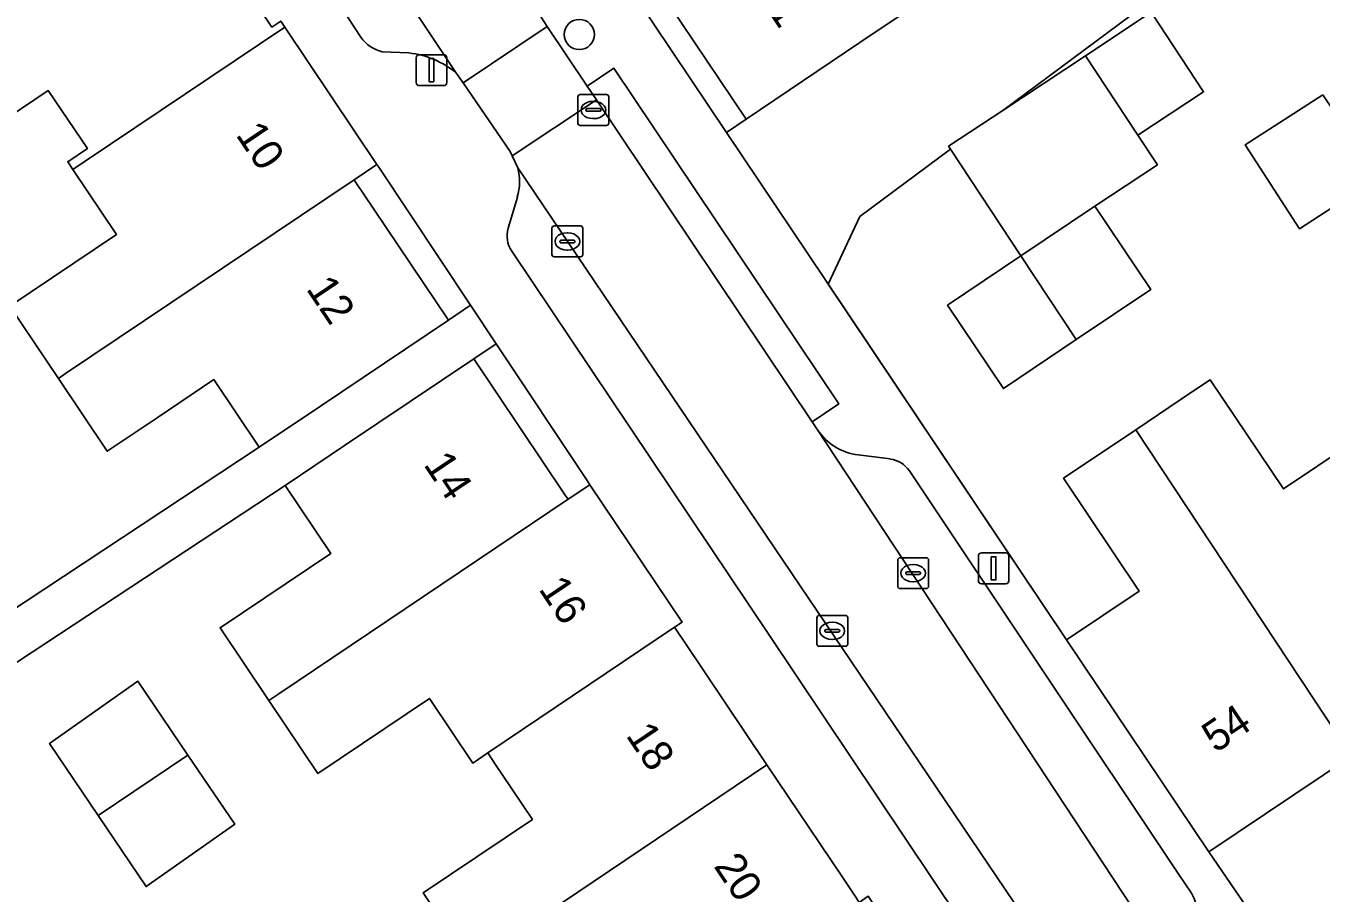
# Model space of a CAD drawing. Extents: x 158352 to 159489, y 383828 to 384603.
# Drawn here: x 158862.39 to 158904.38, y 384139.5 to 384167.59 of the extents above; entities that cross this region are included whole.
import ezdxf

# ---------------------------------------------------------------- set-up
doc = ezdxf.new("R2010")
doc.units = 0
for name, color, linetype in [('IMGEO_Boom', 7, 'Continuous'), ('IMGEO_Erf', 7, 'Continuous'), ('IMGEO_Kolk', 7, 'Continuous'), ('IMGEO_Lichtmast', 7, 'Continuous'), ('IMGEO_Muur', 7, 'Continuous'), ('IMGEO_Pand', 7, 'Continuous'), ('IMGEO_Pand_nummerreeks', 7, 'Continuous'), ('IMGEO_Parkeervlak_open', 7, 'Continuous'), ('IMGEO_Rijbaan_lokaal_open', 7, 'Continuous'), ('IMGEO_Voetpad_open', 7, 'Continuous')]:
    doc.layers.add(name, color=color, linetype=linetype)

msp = doc.modelspace()

# ---------------------------------------------------------------- linework, layer by layer
at = {"layer": 'IMGEO_Boom'}
msp.add_circle((158880.328, 384167.313), 0.489, dxfattribs=at)
at = {"layer": 'IMGEO_Erf'}
for points in [[(158942.263, 384168.715), (158937.66, 384165.622), (158933.069, 384162.537), (158933.874, 384161.338), (158929.263, 384158.239), (158928.917, 384158.007), (158928.717, 384158.105), (158924.553, 384155.307), (158919.952, 384152.215), (158915.351, 384149.124), (158910.891, 384146.127), (158911.02, 384145.936), (158910.878, 384145.84), (158906.196, 384142.695), (158905.358, 384143.942), (158900.735, 384140.836), (158902.964, 384137.583), (158985.981, 384193.365)], [(158907.21, 384174.62), (158894.054, 384164.852), (158896.733, 384166.624), (158898.863, 384168.033), (158900.566, 384165.459), (158898.436, 384164.05), (158899.07, 384163.091), (158897.04, 384161.748), (158898.851, 384159.05), (158896.439, 384157.43), (158894.077, 384155.844), (158892.266, 384158.542), (158894.646, 384160.141), (158892.361, 384163.595), (158889.423, 384161.414), (158888.397, 384159.227), (158896.123, 384147.701), (158898.481, 384149.285), (158896.028, 384152.938), (158898.369, 384154.511), (158900.179, 384155.727), (158900.779, 384156.13), (158903.155, 384152.593), (158905.348, 384154.067)], [(158855.372, 384144.324), (158869.956, 384153.946), (158868.486, 384156.135), (158866.609, 384154.875), (158865.934, 384154.422), (158865.029, 384153.814), (158863.444, 384156.173), (158861.868, 384158.518), (158865.324, 384160.84), (158863.911, 384162.943), (158863.746, 384163.189), (158864.381, 384163.616), (158863.115, 384165.499), (158859.582, 384163.125)], [(158906.237, 384162.682), (158903.677, 384161.02), (158901.912, 384163.736), (158904.435, 384165.362)], [(158876.811, 384137.203), (158875.264, 384139.505), (158878.807, 384141.886), (158877.828, 384143.343), (158877.602, 384143.679), (158877.359, 384144.04), (158876.876, 384143.715), (158875.47, 384145.809), (158871.853, 384143.379), (158870.267, 384145.739), (158868.685, 384148.094), (158872.269, 384150.502), (158870.79, 384152.704), (158856.183, 384143.092)]]:
    msp.add_lwpolyline(points, dxfattribs=at)
for points in [[(158882.786, 384168.968), (158882.152, 384168.541), (158885.101, 384164.143), (158885.743, 384164.573)], [(158873.827, 384163.017), (158873.766, 384163.107), (158873.028, 384162.611), (158873.089, 384162.521), (158873.668, 384161.659), (158876.084, 384158.063), (158876.803, 384158.541)], [(158877.632, 384157.295), (158876.905, 384156.812), (158879.171, 384153.438), (158879.875, 384152.391), (158879.964, 384152.258), (158880.668, 384152.731), (158880.579, 384152.864)], [(158867.639, 384143.972), (158869.158, 384141.73), (158866.287, 384139.711), (158864.727, 384142.014), (158863.15, 384144.342), (158866.021, 384146.361)]]:
    msp.add_lwpolyline(points, close=True, dxfattribs=at)
at = {"layer": 'IMGEO_Kolk'}
for p, q in [((158880.285, 384164.442), (158880.285, 384165.294)), ((158880.36, 384165.368), (158881.212, 384165.368)), ((158881.286, 384165.294), (158881.286, 384164.442)), ((158880.544, 384164.862), (158880.544, 384164.874)), ((158880.982, 384164.825), (158880.584, 384164.825)), ((158880.587, 384164.911), (158880.985, 384164.911)), ((158880.773, 384165.148), (158880.798, 384165.148)), ((158881.028, 384164.874), (158881.028, 384164.862)), ((158880.796, 384164.588), (158880.771, 384164.588)), ((158881.212, 384164.368), (158880.36, 384164.368)), ((158879.442, 384160.185), (158879.442, 384161.037)), ((158879.517, 384161.111), (158880.369, 384161.111)), ((158880.443, 384161.037), (158880.443, 384160.185)), ((158879.701, 384160.605), (158879.701, 384160.617)), ((158879.744, 384160.654), (158880.142, 384160.654)), ((158879.93, 384160.891), (158879.955, 384160.891)), ((158880.185, 384160.617), (158880.185, 384160.605)), ((158880.139, 384160.568), (158879.741, 384160.568)), ((158879.953, 384160.331), (158879.928, 384160.331)), ((158880.369, 384160.111), (158879.517, 384160.111)), ((158890.651, 384149.44), (158890.651, 384150.292)), ((158890.726, 384150.366), (158891.578, 384150.366)), ((158891.139, 384150.146), (158891.164, 384150.146)), ((158891.652, 384150.292), (158891.652, 384149.44)), ((158890.91, 384149.86), (158890.91, 384149.872)), ((158891.348, 384149.823), (158890.95, 384149.823)), ((158890.953, 384149.909), (158891.351, 384149.909)), ((158891.394, 384149.872), (158891.394, 384149.86)), ((158891.578, 384149.366), (158890.726, 384149.366)), ((158891.162, 384149.586), (158891.137, 384149.586)), ((158888.103, 384148.495), (158888.955, 384148.495)), ((158888.028, 384147.569), (158888.028, 384148.421)), ((158888.33, 384148.038), (158888.728, 384148.038)), ((158888.516, 384148.275), (158888.541, 384148.275)), ((158889.029, 384148.421), (158889.029, 384147.569)), ((158888.287, 384147.989), (158888.287, 384148.001)), ((158888.725, 384147.952), (158888.327, 384147.952)), ((158888.539, 384147.715), (158888.514, 384147.715)), ((158888.771, 384148.001), (158888.771, 384147.989)), ((158888.955, 384147.495), (158888.103, 384147.495))]:
    msp.add_line(p, q, dxfattribs=at)
for points in [[(158880.285, 384164.442), (158880.285, 384165.294)], [(158880.36, 384165.368), (158881.212, 384165.368)], [(158881.286, 384165.294), (158881.286, 384164.442)], [(158881.212, 384164.368), (158880.36, 384164.368)], [(158879.442, 384160.185), (158879.442, 384161.037)], [(158879.517, 384161.111), (158880.369, 384161.111)], [(158880.443, 384161.037), (158880.443, 384160.185)], [(158880.369, 384160.111), (158879.517, 384160.111)], [(158890.651, 384149.44), (158890.651, 384150.292)], [(158890.726, 384150.366), (158891.578, 384150.366)], [(158891.652, 384150.292), (158891.652, 384149.44)], [(158891.578, 384149.366), (158890.726, 384149.366)], [(158888.103, 384148.495), (158888.955, 384148.495)], [(158888.028, 384147.569), (158888.028, 384148.421)], [(158889.029, 384148.421), (158889.029, 384147.569)], [(158888.955, 384147.495), (158888.103, 384147.495)]]:
    msp.add_lwpolyline(points, dxfattribs=at)
for centre, radius, start, end in [((158880.362, 384165.292), 0.0765, 91.552, 178.448), ((158880.362, 384165.292), 0.0765, 91.552, 178.448), ((158881.21, 384165.292), 0.0765, 1.552, 88.448), ((158881.21, 384165.292), 0.0765, 1.552, 88.448), ((158880.584, 384164.871), 0.0403, 85.8775, 175.7526), ((158880.581, 384164.861), 0.0366, 178.938, 274.7102), ((158880.985, 384164.868), 0.043, 264.8664, 352.4533), ((158880.989, 384164.873), 0.0386, 1.7309, 96.639), ((158880.362, 384164.444), 0.0765, 181.552, 268.448), ((158880.362, 384164.444), 0.0765, 181.552, 268.448), ((158881.21, 384164.444), 0.0765, 271.552, 358.448), ((158881.21, 384164.444), 0.0765, 271.552, 358.448), ((158879.519, 384161.035), 0.0765, 91.552, 178.448), ((158879.519, 384161.035), 0.0765, 91.552, 178.448), ((158880.367, 384161.035), 0.0765, 1.552, 88.448), ((158880.367, 384161.035), 0.0765, 1.552, 88.448), ((158879.741, 384160.614), 0.0403, 85.8775, 175.7526), ((158880.146, 384160.616), 0.0386, 1.7309, 96.639), ((158879.738, 384160.604), 0.0366, 178.938, 274.7102), ((158880.142, 384160.611), 0.043, 264.8664, 352.4533), ((158879.519, 384160.187), 0.0765, 181.552, 268.448), ((158879.519, 384160.187), 0.0765, 181.552, 268.448), ((158880.367, 384160.187), 0.0765, 271.552, 358.448), ((158880.367, 384160.187), 0.0765, 271.552, 358.448), ((158890.728, 384150.29), 0.0765, 91.552, 178.448), ((158890.728, 384150.29), 0.0765, 91.552, 178.448), ((158891.576, 384150.29), 0.0765, 1.552, 88.448), ((158891.576, 384150.29), 0.0765, 1.552, 88.448), ((158890.95, 384149.869), 0.0403, 85.8775, 175.7526), ((158890.947, 384149.859), 0.0366, 178.938, 274.7102), ((158891.351, 384149.866), 0.043, 264.8664, 352.4533), ((158891.355, 384149.871), 0.0386, 1.7309, 96.639), ((158890.728, 384149.442), 0.0765, 181.552, 268.448), ((158890.728, 384149.442), 0.0765, 181.552, 268.448), ((158891.576, 384149.442), 0.0765, 271.552, 358.448), ((158891.576, 384149.442), 0.0765, 271.552, 358.448), ((158888.105, 384148.419), 0.0765, 91.552, 178.448), ((158888.105, 384148.419), 0.0765, 91.552, 178.448), ((158888.953, 384148.419), 0.0765, 1.552, 88.448), ((158888.953, 384148.419), 0.0765, 1.552, 88.448), ((158888.327, 384147.998), 0.0403, 85.8775, 175.7526), ((158888.732, 384148), 0.0386, 1.7309, 96.639), ((158888.324, 384147.988), 0.0366, 178.938, 274.7102), ((158888.728, 384147.995), 0.043, 264.8664, 352.4533), ((158888.105, 384147.571), 0.0765, 181.552, 268.448), ((158888.105, 384147.571), 0.0765, 181.552, 268.448), ((158888.953, 384147.571), 0.0765, 271.552, 358.448), ((158888.953, 384147.571), 0.0765, 271.552, 358.448)]:
    msp.add_arc(centre, radius, start, end, dxfattribs=at)
for centre, major_axis, ratio, start_param, end_param in [((158880.772, 384164.868), (-0.387, 0.002), 0.722429, 4.712389, 7.853982), ((158880.797, 384164.868), (-0.39, 0.002), 0.717154, 1.570796, 4.712389), ((158879.929, 384160.611), (-0.387, 0.002), 0.722429, 4.712389, 7.853982), ((158879.954, 384160.611), (-0.39, 0.002), 0.717154, 1.570796, 4.712389), ((158891.138, 384149.866), (-0.387, 0.002), 0.722429, 4.712389, 7.853982), ((158891.163, 384149.866), (-0.39, 0.002), 0.717154, 1.570796, 4.712389), ((158888.515, 384147.995), (-0.387, 0.002), 0.722429, 4.712389, 7.853982), ((158888.54, 384147.995), (-0.39, 0.002), 0.717154, 1.570796, 4.712389)]:
    msp.add_ellipse(centre, major_axis=major_axis, ratio=ratio, start_param=start_param, end_param=end_param, dxfattribs=at)
at = {"layer": 'IMGEO_Lichtmast'}
for p, q in [((158875.043, 384165.758), (158875.043, 384166.558)), ((158875.043, 384166.558), (158875.043, 384165.758)), ((158875.143, 384166.658), (158875.933, 384166.658)), ((158875.933, 384166.658), (158875.143, 384166.658)), ((158876.033, 384166.558), (158876.033, 384165.758)), ((158876.033, 384165.758), (158876.033, 384166.558)), ((158875.933, 384165.658), (158875.143, 384165.658)), ((158875.143, 384165.658), (158875.933, 384165.658)), ((158893.265, 384149.619), (158893.265, 384150.419)), ((158893.265, 384150.419), (158893.265, 384149.619)), ((158893.365, 384150.519), (158894.155, 384150.519)), ((158894.155, 384150.519), (158893.365, 384150.519)), ((158894.255, 384150.419), (158894.255, 384149.619)), ((158894.255, 384149.619), (158894.255, 384150.419)), ((158894.155, 384149.519), (158893.365, 384149.519)), ((158893.365, 384149.519), (158894.155, 384149.519))]:
    msp.add_line(p, q, dxfattribs=at)
for points in [[(158875.463, 384166.533), (158875.613, 384166.533), (158875.613, 384165.783), (158875.463, 384165.783), (158875.463, 384166.533)], [(158893.685, 384150.394), (158893.835, 384150.394), (158893.835, 384149.644), (158893.685, 384149.644), (158893.685, 384150.394)]]:
    msp.add_lwpolyline(points, dxfattribs=at)
for centre, start, end in [((158875.143, 384166.558), 90, 180), ((158875.143, 384166.558), 90, 180), ((158875.933, 384166.558), 0, 90), ((158875.933, 384166.558), 360, 90), ((158875.143, 384165.758), 180, 270), ((158875.143, 384165.758), 180, 270), ((158875.933, 384165.758), 270, 0), ((158875.933, 384165.758), 270, 0), ((158893.365, 384150.419), 90, 180), ((158893.365, 384150.419), 90, 180), ((158894.155, 384150.419), 0, 90), ((158894.155, 384150.419), 360, 90), ((158893.365, 384149.619), 180, 270), ((158893.365, 384149.619), 180, 270), ((158894.155, 384149.619), 270, 0), ((158894.155, 384149.619), 270, 0)]:
    msp.add_arc(centre, 0.1, start, end, dxfattribs=at)
at = {"layer": 'IMGEO_Muur'}
msp.add_lwpolyline([(158888.276, 384159.407), (158896.123, 384147.701)], dxfattribs=at)
at = {"layer": 'IMGEO_Pand'}
for points in [[(158882.044, 384168.696), (158882.152, 384168.541), (158882.786, 384168.968), (158885.743, 384164.573), (158889.892, 384167.365), (158891.843, 384168.678), (158890.409, 384170.81), (158893.929, 384173.179), (158892.302, 384175.597)], [(158858.024, 384165.444), (158859.582, 384163.125), (158863.115, 384165.499), (158864.381, 384163.616), (158863.746, 384163.189), (158863.911, 384162.943), (158864.307, 384163.209), (158870.778, 384167.555), (158870.648, 384167.748), (158870.361, 384167.555), (158867.501, 384171.811), (158858.355, 384165.667)], [(158896.733, 384166.624), (158898.411, 384164.087), (158898.436, 384164.05), (158900.566, 384165.459), (158898.863, 384168.033)], [(158873.028, 384162.611), (158873.766, 384163.107), (158870.778, 384167.555), (158864.307, 384163.209), (158863.911, 384162.943), (158865.324, 384160.84), (158861.868, 384158.518), (158863.444, 384156.173), (158863.678, 384156.331)], [(158898.436, 384164.05), (158898.411, 384164.087), (158896.733, 384166.624), (158894.054, 384164.852), (158892.298, 384163.691), (158892.361, 384163.595), (158894.646, 384160.141), (158897.04, 384161.748), (158899.07, 384163.091)], [(158904.435, 384165.362), (158901.912, 384163.736), (158903.677, 384161.02), (158906.237, 384162.682)], [(158873.028, 384162.611), (158863.678, 384156.331), (158863.444, 384156.173), (158865.029, 384153.814), (158865.934, 384154.422), (158866.609, 384154.875), (158868.486, 384156.135), (158869.956, 384153.946), (158871.934, 384155.275), (158876.084, 384158.063), (158873.668, 384161.659), (158873.089, 384162.521)], [(158894.646, 384160.141), (158896.439, 384157.43), (158898.851, 384159.05), (158897.04, 384161.748)], [(158894.646, 384160.141), (158892.266, 384158.542), (158894.077, 384155.844), (158896.439, 384157.43)], [(158879.964, 384152.258), (158879.875, 384152.391), (158879.171, 384153.438), (158876.905, 384156.812), (158872.755, 384154.024), (158870.79, 384152.704), (158872.269, 384150.502), (158868.685, 384148.094), (158870.267, 384145.739), (158870.586, 384145.953)], [(158906.084, 384152.973), (158905.348, 384154.067), (158903.155, 384152.593), (158900.779, 384156.13), (158900.179, 384155.727), (158898.369, 384154.511), (158905.358, 384143.942), (158906.196, 384142.695), (158910.878, 384145.84)], [(158905.358, 384143.942), (158898.369, 384154.511), (158896.028, 384152.938), (158898.481, 384149.285), (158896.123, 384147.701), (158900.735, 384140.836)], [(158883.417, 384148.111), (158883.662, 384148.276), (158880.668, 384152.731), (158879.964, 384152.258), (158870.586, 384145.953), (158870.267, 384145.739), (158871.853, 384143.379), (158875.47, 384145.809), (158876.876, 384143.715), (158877.359, 384144.04)], [(158886.41, 384143.657), (158883.729, 384147.646), (158883.501, 384147.986), (158883.417, 384148.111), (158877.359, 384144.04), (158877.602, 384143.679), (158877.828, 384143.343), (158878.807, 384141.886), (158875.264, 384139.505), (158876.811, 384137.203), (158877.197, 384137.463)], [(158864.727, 384142.014), (158867.639, 384143.972), (158866.021, 384146.361), (158863.15, 384144.342)], [(158864.727, 384142.014), (158866.287, 384139.711), (158869.158, 384141.73), (158867.639, 384143.972)], [(158889.404, 384139.201), (158889.293, 384139.366), (158888.836, 384140.046), (158886.41, 384143.657), (158877.197, 384137.463), (158876.811, 384137.203), (158878.423, 384134.804), (158881.967, 384137.186), (158883.348, 384135.13)]]:
    msp.add_lwpolyline(points, close=True, dxfattribs=at)
at = {"layer": 'IMGEO_Parkeervlak_open'}
for points in [[(158876.351, 384166.052), (158876.113, 384166.409), (158862.48, 384186.854)], [(158861.63, 384184.958), (158873.249, 384167.231)], [(158873.94, 384166.752), (158874.808, 384166.715)], [(158898.842, 384132.651), (158878.334, 384162.992)], [(158878.32, 384162.047), (158878.023, 384161.043)], [(158878.138, 384160.295), (158886.499, 384147.841), (158894.388, 384136.057), (158895.769, 384133.994)], [(158888.055, 384154.504), (158900.101, 384136.239)], [(158890.408, 384153.563), (158889.366, 384153.695)], [(158900.172, 384139.502), (158899.767, 384140.107), (158891.029, 384153.179)]]:
    msp.add_lwpolyline(points, dxfattribs=at)
for centre, radius, start, end in [((158874.24, 384167.923), 1.209, 214.9225, 255.6182), ((158874.506, 384163.886), 2.846, 49.5842, 83.9111), ((158876.642, 384162.544), 1.75, 343.4873, 14.8152), ((158878.876, 384160.791), 0.889, 163.5621, 213.9187), ((158889.598, 384155.538), 1.858, 213.8247, 262.819), ((158890.295, 384152.685), 0.885, 33.9048, 82.6335), ((158899.467, 384139.027), 0.85, 340.9972, 34.0024)]:
    msp.add_arc(centre, radius, start, end, dxfattribs=at)
at = {"layer": 'IMGEO_Rijbaan_lokaal_open'}
for points in [[(158865.197, 384188.669), (158862.48, 384186.854), (158876.113, 384166.409), (158876.351, 384166.052), (158876.56, 384165.749), (158879.291, 384167.574), (158879, 384168.028)], [(158880.587, 384165.641), (158879.291, 384167.574), (158876.56, 384165.749), (158878.091, 384163.528), (158878.157, 384163.383), (158880.883, 384165.199)]]:
    msp.add_lwpolyline(points, close=True, dxfattribs=at)
for points in [[(158888.055, 384154.504), (158887.877, 384154.77), (158880.883, 384165.199), (158878.157, 384163.383), (158878.334, 384162.992), (158898.842, 384132.651), (158901.467, 384128.786), (158904.315, 384134.226)], [(158900.779, 384135.251), (158900.452, 384135.707), (158900.101, 384136.239), (158888.055, 384154.504)]]:
    msp.add_lwpolyline(points, dxfattribs=at)
at = {"layer": 'IMGEO_Voetpad_open'}
for points in [[(158904.315, 384134.226), (158902.964, 384137.583), (158900.735, 384140.836), (158896.123, 384147.701), (158888.397, 384159.227), (158888.276, 384159.407), (158885.101, 384164.143), (158882.152, 384168.541), (158882.044, 384168.696), (158878.986, 384173.105), (158878.901, 384173.228), (158879.176, 384173.413), (158876.265, 384177.74), (158873.389, 384182.013), (158873.102, 384181.819), (158872.982, 384181.998), (158869.987, 384186.448), (158869.896, 384186.584), (158866.941, 384191.013), (158866.244, 384192.057), (158864.445, 384194.753), (158857.143, 384205.697), (158852.538, 384212.577)], [(158873.249, 384167.231), (158861.63, 384184.958)], [(158867.501, 384171.811), (158870.361, 384167.555), (158870.648, 384167.748), (158870.778, 384167.555), (158873.766, 384163.107), (158873.827, 384163.017), (158876.803, 384158.541), (158877.632, 384157.295), (158880.579, 384152.864), (158880.668, 384152.731), (158883.662, 384148.276), (158883.417, 384148.111), (158883.501, 384147.986), (158883.729, 384147.646), (158886.41, 384143.657), (158888.836, 384140.046), (158889.293, 384139.366), (158889.404, 384139.201), (158889.698, 384139.399), (158892.764, 384134.835), (158895.741, 384130.365), (158896.445, 384129.308), (158898.923, 384125.588), (158908.084, 384120.639)], [(158879, 384168.028), (158879.291, 384167.574), (158880.587, 384165.641), (158881.451, 384166.22), (158888.741, 384155.349), (158887.877, 384154.77), (158888.055, 384154.504)], [(158874.808, 384166.715), (158873.94, 384166.752)], [(158878.334, 384162.992), (158878.157, 384163.383), (158878.091, 384163.528), (158876.56, 384165.749), (158876.351, 384166.052)], [(158878.023, 384161.043), (158878.32, 384162.047)], [(158895.769, 384133.994), (158894.388, 384136.057), (158886.499, 384147.841), (158878.138, 384160.295)], [(158858.266, 384134.119), (158872.435, 384112.771), (158887.133, 384123.108), (158889.074, 384124.4), (158893.236, 384127.17), (158896.445, 384129.308), (158895.741, 384130.365), (158892.634, 384128.295), (158888.484, 384125.506), (158886.43, 384124.126), (158874.109, 384115.848), (158856.183, 384143.092), (158870.79, 384152.704), (158872.755, 384154.024), (158876.905, 384156.812), (158877.632, 384157.295), (158876.803, 384158.541), (158876.084, 384158.063), (158871.934, 384155.275), (158869.956, 384153.946), (158855.372, 384144.324)], [(158889.366, 384153.695), (158890.408, 384153.563)], [(158891.029, 384153.179), (158899.767, 384140.107), (158900.172, 384139.502)]]:
    msp.add_lwpolyline(points, dxfattribs=at)
for points in [[(158909.235, 384177.475), (158914.56, 384179.588), (158919.051, 384182.562), (158918.866, 384182.836), (158923.473, 384185.949), (158921.488, 384188.742), (158910.432, 384180.884), (158906.648, 384181.891), (158902.227, 384188.365), (158900.806, 384187.395), (158905.594, 384180.385), (158894.883, 384170.872), (158891.843, 384168.678), (158889.892, 384167.365), (158885.743, 384164.573), (158885.101, 384164.143), (158888.276, 384159.407), (158888.397, 384159.227), (158889.423, 384161.414), (158892.361, 384163.595), (158892.298, 384163.691), (158894.054, 384164.852), (158907.21, 384174.62), (158908.345, 384175.773)], [(158880.587, 384165.641), (158880.883, 384165.199), (158887.877, 384154.77), (158888.741, 384155.349), (158881.451, 384166.22)]]:
    msp.add_lwpolyline(points, close=True, dxfattribs=at)
for centre, radius, start, end in [((158874.24, 384167.923), 1.209, 214.9225, 255.6182), ((158874.506, 384163.886), 2.846, 49.5842, 83.9111), ((158876.642, 384162.544), 1.75, 343.4873, 14.8152), ((158878.876, 384160.791), 0.889, 163.5621, 213.9187), ((158889.598, 384155.538), 1.858, 213.8247, 262.819), ((158890.295, 384152.685), 0.885, 33.9048, 82.6335), ((158899.467, 384139.027), 0.85, 340.9972, 34.0024)]:
    msp.add_arc(centre, radius, start, end, dxfattribs=at)

# ---------------------------------------------------------------- texts
at = {"layer": 'IMGEO_Pand_nummerreeks'}
for s, rotation, p in [('11', 303.9331, (158886.009, 384168.692)), ('10', 303.9017, (158869.171, 384164.065)), ('12', 303.896, (158871.452, 384159.076)), ('14', 303.8902, (158875.258, 384153.382)), ('16', 303.9017, (158878.988, 384149.351)), ('54', 33.8955, (158900.955, 384144.02)), ('18', 303.896, (158881.818, 384144.61)), ('20', 303.896, (158884.664, 384140.375))]:
    msp.add_text(s, height=1, rotation=rotation, dxfattribs=at).set_placement(p)

doc.saveas('drawing.dxf')
